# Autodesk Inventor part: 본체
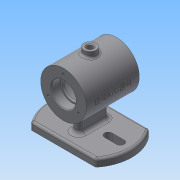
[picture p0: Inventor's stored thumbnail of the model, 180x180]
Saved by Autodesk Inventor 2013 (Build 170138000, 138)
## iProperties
Created: 2017-12
Part Number: 본체
Material: 일반
Document SubType Name: Modeling
Designer: Administrator
Density: 1 g/cm^3
Author: Administrator
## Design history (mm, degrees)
sketch "스케치1"
  geometry: C1 r 30 at (0, 0); 1 further point
  constraints: 1 centre point, 1 coincident
  dimensions: "d0" = 60 diameter of C1
extrude "돌출1" new body sketch "스케치1" stored distance "d2" = 70; taper "d3" = 0 deg
hole "구멍1" diameter "d6" = 28; stored, may be unused: countersink angle "d10" = 90 deg, drill point angle "d12" = 118 deg; dims "d4" = 10, "d5" = 10, "d7" = 6, "d8" = 32, "d9" = 12, "d11" = 8
hole "구멍2" diameter "d15" = 32; stored, may be unused: countersink angle "d19" = 90 deg, drill point angle "d21" = 0 deg; dims "d13" = 10, "d14" = 10, "d16" = 6, "d17" = 32, "d18" = 12, "d20" = 12
node "작업 평면1"
sketch "스케치2"
  geometry: L1 (-42.426, -35)-(42.426, -35); L2 (-42.426, 35)-(42.426, 35); A1 r 55 centre (0, 0) between (42.426, -35) and (42.426, 35); A2 r 55 centre (0, 0) between (-42.426, 35) and (-42.426, -35); 1 further point
  constraints: 4 end point, 4 point on circle, 2 centre point, 1 coincident, 1 horizontal, 1 parallel
  dimensions: "d24" = 35 distance from line of L1 A1.centre; "d25" = 35 distance from line of L2 point (0, 0); "d26" = 55 radius of A2; "d27" = 55 radius of A1
extrude "돌출2" join sketch "스케치2" distance "d28" = 10; taper "d29" = 0 deg
sketch "스케치3"
  geometry: L1 (0, -20)-(0, -20); L2 (5, -15)-(5, 15); L3 (0, 20)-(0, 20); L4 (-5, 15)-(-5, -15); A1 r 55 centre (0, 0) between (42.426, -35) and (42.426, 35) reference; A2 r 5 centre (0, -15) between (-5, -15) and (0, -20); A3 r 5 centre (0, -15) between (0, -20) and (5, -15); A4 r 5 centre (0, 15) between (0, 20) and (-5, 15); A5 r 5 centre (0, 15) between (5, 15) and (0, 20); 5 further points
  constraints: 8 end point, 8 point on circle, 8 tangent, 6 point on line, 4 centre point, 3 equal radius, 2 midpoint, 2 parallel, 1 horizontal, 1 horizontal alignment, 1 perpendicular, 1 vertical alignment
  dimensions: "d30" = 10 distance of point (5, 20) point (-5, 20); "d32" = 40 distance of point (-5, 20) point (-5, -20); "d33" = 5 radius of A2
extrude "돌출3" join sketch "스케치3" stored distance "d34" = 10; taper "d35" = 0 deg
sketch "스케치4"
  geometry: L1 (-20, 25)-(20, 25); L2 (20, 25)-(20, 0); L3 (20, 0)-(-20, 0); L4 (-20, 0)-(-20, 25); 2 further points
  constraints: 8 end point, 2 coincident, 2 parallel, 1 horizontal, 1 midpoint, 1 perpendicular
  dimensions: "d36" = 25 distance of L1.end L2.end; "d38" = 40 distance of L1.start L1.end
revolve "회전1" sketch "스케치4" stored, may be unused: angle "d39" = 90 deg
node "작업 평면2"
sketch "스케치5"
  geometry: C1 r 8 at (0, 0); 1 further point
  constraints: 1 centre point, 1 coincident
  dimensions: "d41" = 16 diameter of C1
extrude "돌출4" join sketch "스케치5" stored distance "d42" = 10; taper "d43" = 0 deg
hole "구멍3" diameter "d46" = 8; stored, may be unused: countersink angle "d50" = 90 deg, drill point angle "d52" = 0 deg; dims "d44" = 10, "d45" = 10, "d47" = 6, "d48" = 32, "d49" = 12, "d51" = 25
sketch "스케치6"
  geometry: L1 (-40, -5)-(-24, -5); L2 (-19, 0)-(-19, 0); L3 (-24, 5)-(-40, 5); L4 (-45, 0)-(-45, 0); A1 r 55 centre (0, 0) between (42.426, -35) and (42.426, 35) reference; A2 r 5 centre (-40, 0) between (-45, 0) and (-40, -5); A3 r 5 centre (-40, 0) between (-40, 5) and (-45, 0); A4 r 5 centre (-24, 0) between (-19, 0) and (-24, 5); A5 r 5 centre (-24, 0) between (-24, -5) and (-19, 0); 4 further points
  constraints: 8 end point, 8 point on circle, 8 tangent, 6 point on line, 4 centre point, 3 equal radius, 2 parallel, 1 horizontal, 1 horizontal alignment, 1 midpoint, 1 perpendicular
  dimensions: "d53" = 19 distance from line of L2 A1.centre; "d54" = 26 distance of point (-19, 5) point (-45, 5); "d55" = 10 distance of point (-45, 5) point (-45, -5); "d56" = 5 radius of A2
extrude "돌출5" cut sketch "스케치6" stored distance "d57" = 10; taper "d58" = 0 deg
sketch "스케치7"
  geometry: C1 r 16 at (0, 0) reference; 1 further point
  constraints: 1 vertical alignment
  dimensions: "d59" = 23 distance of point (0, 23) C1.centre
hole "구멍4" sketch "스케치7" at (0, 23) diameter "d60" = 3.242; stored, may be unused: countersink angle "d64" = 90 deg, drill point angle "d66" = 0 deg; dims "d61" = 8, "d62" = 32, "d63" = 12, "d65" = 10
fillet "모깎기1" dims "d70" = 5
fillet "모깎기2" dims "d71" = 3
fillet "모깎기3" dims "d72" = 3
fillet "모깎기4" dims "d73" = 3
fillet "모깎기5" dims "d74" = 0.3
fillet "모깎기6" dims "d75" = 3
chamfer "모따기1" distance "d76" = 1; stored, may be unused: second distance "d77" = 2, angle "d78" = 45 deg
node "작업 평면3"
sketch "스케치8"
  geometry: L1 (-35, 30)-(35, 30) reference; L2 (-35, 30)-(-35, -30) reference; 2 further points
  constraints: 1 other
  dimensions: "d80" = 30 distance from line of L1 point (0, 0); "d81" = 35 distance from line of L2 point (0, 0)
feature "엠보싱1" sketch "스케치8" dims "d82" = 0.5, "d83" = 0
node "솔리드1"
mirror "대칭1"
pattern_circular "원형 패턴1" dims angle "d68" = 360 deg
mirror "대칭2"
other parameters: "d22" = -62, "d40" = 37
